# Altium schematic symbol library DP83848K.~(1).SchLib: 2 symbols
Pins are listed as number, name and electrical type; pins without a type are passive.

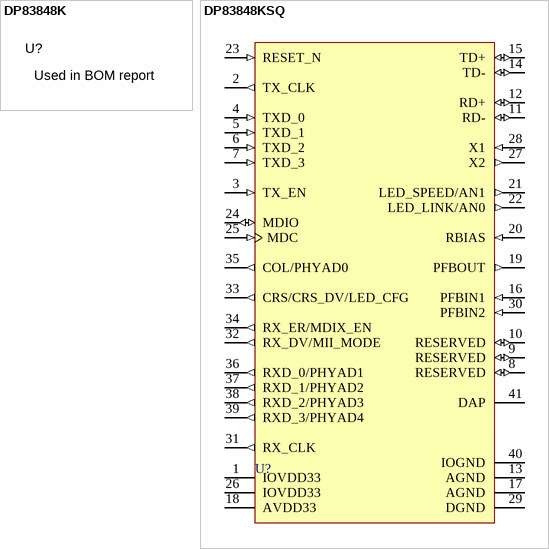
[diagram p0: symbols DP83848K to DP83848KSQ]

## DP83848K
designator U?, comment Used in BOM report
SymbolVersion: use current date i.e. 2008-05-20; SymbolCreator: Use a-id; CompType: Used in some BOM reports.  Useful for finding later.; U/M: EA, IN, or GM

## DP83848KSQ
designator U?
PHYTER?Mini LS Industrial Temperature Single Port 10/100 Mb/s Ethernet Transceiver, 40-pin LLP; PartNumber: DP83848KSQ; Manufacturer: National Semiconductor; PackageTopMarking: NS*UZXYTT*83848KSQ; PowerWise: N; CompType: Interface IC
footprint SQA40B (QFN, 40-Leads, Body 6x6mm, Pitch 0.5mm, NSC Recommended)
pins: 1 IOVDD33 (power), 2 TX_CLK (out), 3 TX_EN (in), 4 TXD_0 (in), 5 TXD_1 (in), 6 TXD_2 (in), 7 TXD_3 (in), 8 RESERVED (io), 9 RESERVED (io), 10 RESERVED (io), 11 RD- (io), 12 RD+ (io), 13 AGND (power), 14 TD- (io), 15 TD+ (io), 16 PFBIN1 (in), 17 AGND (power), 18 AVDD33 (power), 19 PFBOUT (out), 20 RBIAS (in), 21 LED_SPEED/AN1 (out), 22 LED_LINK/AN0 (out), 23 RESET_N (in), 24 MDIO (io), 25 MDC (in), 26 IOVDD33 (power), 27 X2 (out), 28 X1 (in), 29 DGND (power), 30 PFBIN2 (in), 31 RX_CLK (out), 32 RX_DV/MII_MODE (out), 33 CRS/CRS_DV/LED_CFG (out), 34 RX_ER/MDIX_EN (out), 35 COL/PHYAD0 (out), 36 RXD_0/PHYAD1 (out), 37 RXD_1/PHYAD2 (out), 38 RXD_2/PHYAD3 (out), 39 RXD_3/PHYAD4 (out), 40 IOGND (power), 41 DAP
